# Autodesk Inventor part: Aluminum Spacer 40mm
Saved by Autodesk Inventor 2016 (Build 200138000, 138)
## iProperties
Created: 2016-01
Part Number: Aluminum Spacer 40mm
Material: Generic
Document SubType Name: Modeling
Designer: John
Density: 1 g/cm^3
Appearance: Default
Author: John
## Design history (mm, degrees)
feature "CHAMFER1"
body "Solid1"
